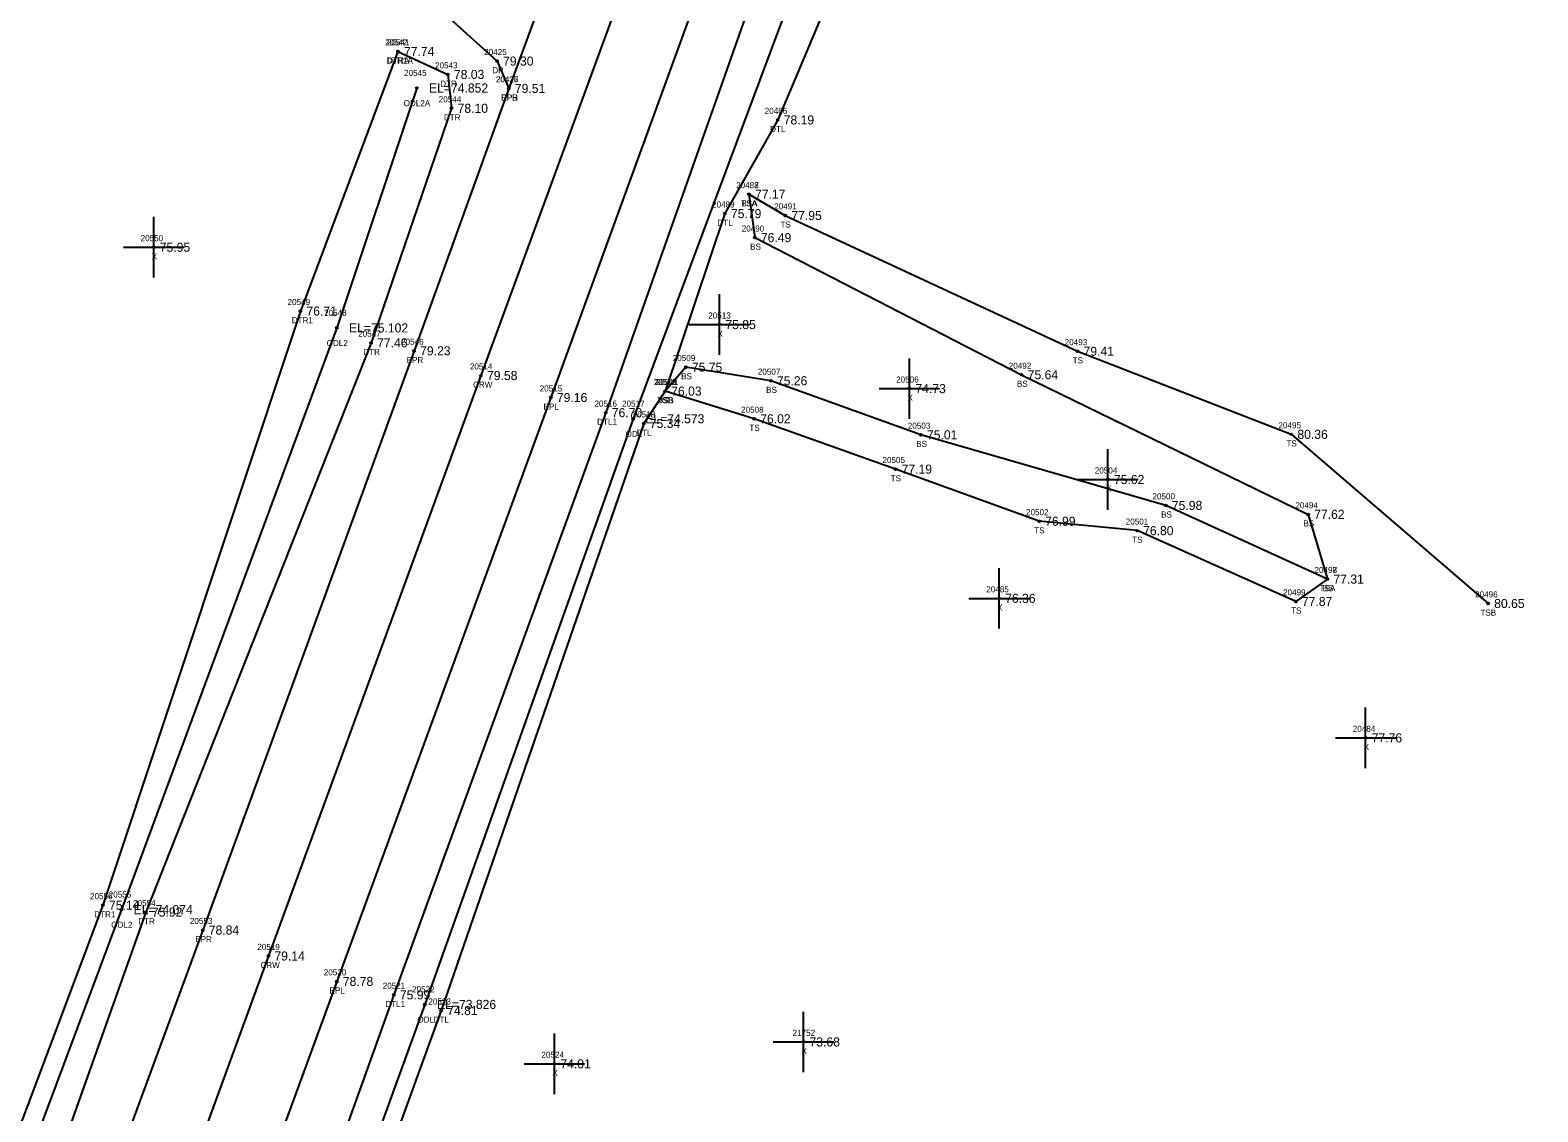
# Model space of a CAD drawing. Extents: x 2140110 to 2141565, y 506241 to 510327.
# Drawn here: x 2140964.5 to 2141213.4, y 509154.8 to 509333.5 of the extents above; entities that cross this region are included whole.
import ezdxf

# ---------------------------------------------------------------- set-up
doc = ezdxf.new("R2010")
doc.units = 0
for name, color, linetype in [('RD_DTM_BkLn1', 7, 'Continuous'), ('RD_DTM_BkLn2', 7, 'Continuous'), ('RD_DTM_BkLn_txCode', 7, 'Continuous'), ('RD_EX_Driveway', 7, 'Continuous'), ('RD_EX_Driveway_txCode', 7, 'Continuous'), ('RD_EX_H2O', 7, 'Continuous'), ('RD_EX_H2O_txCode', 7, 'Continuous'), ('RD_EX_Misc', 7, 'Continuous'), ('RD_EX_Misc_txCode', 7, 'Continuous'), ('RD_EX_Road', 7, 'Continuous'), ('RD_EX_Road_txCode', 7, 'Continuous'), ('RD_EX_TX_Driveway_ELEV', 7, 'Continuous'), ('RD_EX_TX_H2O_ELEV', 7, 'Continuous'), ('RD_EX_TX_Misc_ELEV', 7, 'Continuous'), ('RD_EX_TX_Road_ELEV', 7, 'Continuous'), ('RD_HC_Survey_ELEV', 7, 'Continuous'), ('RD_HC_Survey_txCode', 7, 'Continuous'), ('RD_SMD_Locator', 7, 'Continuous')]:
    doc.layers.add(name, color=color, linetype=linetype)

msp = doc.modelspace()

# ---------------------------------------------------------------- linework, layer by layer
at = {"layer": 'RD_DTM_BkLn1'}
msp.add_lwpolyline([(2141401.24, 510292.17), (2141386.62, 510241.55), (2141370.29, 510189.18), (2141352.34, 510135.64), (2141334.07, 510083.82), (2141314.82, 510031.25), (2141297.4, 509983.45), (2141260.01, 509880.66), (2141224.45, 509783.3), (2141187.1, 509681.41), (2141150.45, 509581.24), (2141112.96, 509478.26), (2141074.89, 509374.78), (2141038.89, 509276.46), (2141003.79, 509180.59), (2140969.89, 509087.8), (2140962.46, 509066.85), (2140921.91, 508956.12), (2140885.66, 508857.72), (2140850.55, 508762.05)], dxfattribs=at)
at = {"layer": 'RD_DTM_BkLn2'}
for points in [[(2141083.13, 509306.4), (2141084.1, 509299.24), (2141128.15, 509276.59), (2141175.44, 509253.53), (2141178.62, 509242.84), (2141151.95, 509255.01), (2141111.52, 509266.67), (2141086.75, 509275.6), (2141072.71, 509277.85), (2141069.29, 509273.89)], [(2141083.13, 509306.4), (2141089.13, 509302.9), (2141137.37, 509280.47), (2141172.67, 509266.75), (2141205.16, 509238.81)], [(2141178.62, 509242.84), (2141173.42, 509239.15), (2141147.2, 509250.84), (2141131.03, 509252.39), (2141107.33, 509261), (2141083.99, 509269.32), (2141069.29, 509273.89)]]:
    msp.add_lwpolyline(points, dxfattribs=at)
at = {"layer": 'RD_EX_Driveway'}
msp.add_lwpolyline([(2141052.52, 509348.48), (2141045.04, 509346.63), (2141037.37, 509348.41), (2141026.29, 509351.7), (2141022.22, 509343.44), (2141033.2, 509335.93), (2141041.54, 509328.4), (2141043.48, 509323.88)], dxfattribs=at)
at = {"layer": 'RD_EX_H2O'}
for points in [[(2141109.57, 509415.73), (2141114.37, 509420.62), (2141120.58, 509418.47), (2141123.73, 509414.72), (2141106.65, 509363.28), (2141087.87, 509318.68), (2141079.16, 509303.21), (2141069.29, 509273.89), (2141065.76, 509268.54), (2141032.31, 509171.57), (2140998.87, 509079.36), (2140999.1, 509067.34)], [(2141109.57, 509415.73), (2141094.19, 509368.74), (2141059.48, 509270.33), (2141024.5, 509174.17), (2140991.17, 509081.19), (2140987.7, 509072.11)], [(2141117.74, 509414.57), (2141100.21, 509366.33), (2141064.01, 509269.32), (2141029.63, 509172.59), (2140996.02, 509080.04), (2140996.76, 509067.73)], [(2141025.18, 509330), (2141009.08, 509287.11), (2140976.48, 509188.97), (2140943.34, 509100.91), (2140941.69, 509092.55)], [(2141025.18, 509330), (2141033.42, 509326.19), (2141034.03, 509320.6), (2141020.74, 509281.87), (2140983.57, 509187.83), (2140949.44, 509091.79), (2140950.12, 509084.29)], [(2141028.31, 509323.95), (2141015.1, 509284.32), (2140979.54, 509188.24), (2140943.06, 509090.7)]]:
    msp.add_lwpolyline(points, dxfattribs=at)
at = {"layer": 'RD_EX_Misc'}
for p, q in [((2140984.86, 509292.65), (2140984.86, 509302.65)), ((2140979.86, 509297.65), (2140989.86, 509297.65)), ((2141078.24, 509279.88), (2141078.24, 509289.88)), ((2141073.24, 509284.88), (2141083.24, 509284.88)), ((2141109.61, 509269.3), (2141109.61, 509279.3)), ((2141104.61, 509274.3), (2141114.61, 509274.3)), ((2141142.38, 509254.28), (2141142.38, 509264.28)), ((2141137.38, 509259.28), (2141147.38, 509259.28)), ((2141124.42, 509234.66), (2141124.42, 509244.66)), ((2141119.42, 509239.66), (2141129.42, 509239.66)), ((2141184.94, 509211.61), (2141184.94, 509221.61)), ((2141179.94, 509216.61), (2141189.94, 509216.61)), ((2141092.13, 509161.39), (2141092.13, 509171.39)), ((2141051, 509157.78), (2141051, 509167.78)), ((2141087.13, 509166.39), (2141097.13, 509166.39)), ((2141046, 509162.78), (2141056, 509162.78))]:
    msp.add_line(p, q, dxfattribs=at)
at = {"layer": 'RD_EX_Road'}
for points in [[(2141175.93, 509686.04), (2141140.09, 509588.3), (2141106.08, 509494.11), (2141096.82, 509469.24), (2141063.82, 509378.98), (2141052.52, 509348.48), (2141043.48, 509323.88), (2141027.84, 509280.54), (2140992.95, 509184.87), (2140958.53, 509091.45), (2140950.8, 509069.47), (2140944.28, 509052.06), (2140911.45, 508962.1), (2140874.65, 508861.6), (2140839.42, 508765.22), (2140802.38, 508664.56)], [(2141197.99, 509676.56), (2141193.66, 509664.6), (2141161.61, 509577.24), (2141123.75, 509473.61), (2141115.5, 509450.65), (2141102.09, 509414.61), (2141086.27, 509371.27), (2141050.42, 509272.83), (2141015.08, 509176.39), (2140981.03, 509083.35), (2140979.15, 509077.9), (2140973.7, 509063.54), (2140966.53, 509043.25), (2140933.44, 508952.99), (2140896.92, 508852.59), (2140862.18, 508757.77)]]:
    msp.add_lwpolyline(points, dxfattribs=at)
at = {"layer": 'RD_SMD_Locator'}
for centre in [(2141025.18, 509330), (2141025.18, 509330), (2141041.54, 509328.4), (2141033.42, 509326.19), (2141028.31, 509323.95), (2141043.48, 509323.88), (2141043.48, 509323.88), (2141034.03, 509320.6), (2141087.87, 509318.68), (2141083.13, 509306.4), (2141083.13, 509306.4), (2141079.16, 509303.21), (2141089.13, 509302.9), (2140984.86, 509297.65), (2141084.1, 509299.24), (2141009.08, 509287.11), (2141078.24, 509284.88), (2141015.1, 509284.32), (2141020.74, 509281.87), (2141027.84, 509280.54), (2141137.37, 509280.47), (2141072.71, 509277.85), (2141038.89, 509276.46), (2141086.75, 509275.6), (2141128.15, 509276.59), (2141050.42, 509272.83), (2141069.29, 509273.89), (2141069.29, 509273.89), (2141069.29, 509273.89), (2141109.61, 509274.3), (2141059.48, 509270.33), (2141064.01, 509269.32), (2141065.76, 509268.54), (2141083.99, 509269.32), (2141111.52, 509266.67), (2141172.67, 509266.75), (2141107.33, 509261), (2141142.38, 509259.28), (2141151.95, 509255.01), (2141131.03, 509252.39), (2141175.44, 509253.53), (2141147.2, 509250.84), (2141178.62, 509242.84), (2141178.62, 509242.84), (2141124.42, 509239.66), (2141173.42, 509239.15), (2141205.16, 509238.81), (2141184.94, 509216.61), (2140976.48, 509188.97), (2140979.54, 509188.24), (2140983.57, 509187.83), (2140992.95, 509184.87), (2141003.79, 509180.59), (2141015.08, 509176.39), (2141024.5, 509174.17), (2141029.63, 509172.59), (2141032.31, 509171.57), (2141092.13, 509166.39), (2141051, 509162.78)]:
    msp.add_circle(centre, 0.15, dxfattribs=at)

# ---------------------------------------------------------------- texts
at = {"layer": 'RD_DTM_BkLn_txCode'}
for s, p in [('20487', (2141081.01, 509307.4)), ('20488', (2141081.01, 509307.4)), ('TSA', (2141081.85, 509304.4)), ('BSA', (2141081.86, 509304.4)), ('20491', (2141087.29, 509303.9)), ('20490', (2141081.94, 509300.24)), ('TS', (2141088.33, 509300.9)), ('BS', (2141083.32, 509297.24)), ('20493', (2141135.25, 509281.47)), ('20509', (2141070.55, 509278.85)), ('20507', (2141084.6, 509276.6)), ('20492', (2141126.03, 509277.59)), ('TS', (2141136.57, 509278.47)), ('20510', (2141067.42, 509274.89)), ('20511', (2141067.74, 509274.89)), ('BS', (2141071.93, 509275.85)), ('BS', (2141127.37, 509274.59)), ('TSB', (2141068.02, 509271.89)), ('BSB', (2141068.04, 509271.89)), ('BS', (2141085.97, 509273.6)), ('20508', (2141081.83, 509270.32)), ('TS', (2141083.2, 509267.32)), ('20503', (2141109.36, 509267.67)), ('20495', (2141170.55, 509267.75)), ('BS', (2141110.74, 509264.67)), ('TS', (2141171.87, 509264.75)), ('20505', (2141105.17, 509262)), ('TS', (2141106.53, 509259)), ('20500', (2141149.75, 509256.01)), ('20494', (2141173.33, 509254.53)), ('20502', (2141128.87, 509253.39)), ('20501', (2141145.33, 509251.84)), ('BS', (2141151.17, 509253.01)), ('BS', (2141174.66, 509251.53)), ('TS', (2141130.23, 509250.39)), ('TS', (2141146.41, 509248.84)), ('20497', (2141176.5, 509243.84)), ('20498', (2141176.5, 509243.84)), ('20499', (2141171.3, 509240.15)), ('TSA', (2141177.34, 509240.84)), ('BS', (2141177.84, 509240.84)), ('20496', (2141203.01, 509239.81)), ('TS', (2141172.63, 509237.15)), ('TSB', (2141203.89, 509236.81))]:
    msp.add_text(s, height=1, dxfattribs=at).set_placement(p)
at = {"layer": 'RD_EX_Driveway_txCode'}
for s, p in [('20425', (2141039.42, 509329.4)), ('DP', (2141040.76, 509326.4)), ('20426', (2141041.33, 509324.88)), ('DPB', (2141042.22, 509321.88))]:
    msp.add_text(s, height=1, dxfattribs=at).set_placement(p)
at = {"layer": 'RD_EX_H2O_txCode'}
for s, p in [('20542', (2141023.06, 509331)), ('20541', (2141023.35, 509331)), ('DTR1A', (2141023.26, 509328)), ('DTRA', (2141023.42, 509328)), ('20543', (2141031.3, 509327.19)), ('20545', (2141026.19, 509325.95)), ('DTR', (2141032.16, 509324.19)), ('20544', (2141031.91, 509321.6)), ('ODL2A', (2141026.12, 509320.95)), ('DTR', (2141032.76, 509318.6)), ('20486', (2141085.73, 509319.68)), ('DTL', (2141086.63, 509316.68)), ('20489', (2141077.04, 509304.21)), ('DTL', (2141077.92, 509301.21)), ('20549', (2141006.96, 509288.11)), ('20548', (2141012.99, 509286.32)), ('DTR1', (2141007.65, 509285.11)), ('ODL2', (2141013.41, 509281.32)), ('20547', (2141018.62, 509282.87)), ('DTR', (2141019.47, 509279.87)), ('20512', (2141067.46, 509274.89)), ('20516', (2141057.62, 509271.33)), ('20517', (2141062.17, 509271.32)), ('DTL', (2141068.05, 509271.89)), ('20518', (2141063.93, 509269.54)), ('DTL1', (2141058.07, 509268.33)), ('ODL', (2141062.76, 509266.32)), ('DTL', (2141064.52, 509266.54)), ('20556', (2140974.34, 509189.97)), ('20555', (2140977.43, 509190.24)), ('DTR1', (2140975.05, 509186.97)), ('20554', (2140981.45, 509188.83)), ('ODL2', (2140977.85, 509185.24)), ('DTR', (2140982.3, 509185.83)), ('20521', (2141022.66, 509175.17)), ('20522', (2141027.51, 509174.59)), ('DTL1', (2141023.09, 509172.17)), ('20523', (2141030.2, 509172.57)), ('ODL', (2141028.39, 509169.59)), ('DTL', (2141031.07, 509169.57))]:
    msp.add_text(s, height=1, dxfattribs=at).set_placement(p)
at = {"layer": 'RD_EX_Misc_txCode'}
for s, p in [('20550', (2140982.7, 509298.65)), ('X', (2140984.54, 509295.65)), ('20513', (2141076.41, 509285.88)), ('X', (2141077.93, 509282.88)), ('20506', (2141107.43, 509275.3)), ('X', (2141109.3, 509272.3)), ('20504', (2141140.23, 509260.28)), ('X', (2141142.07, 509257.28)), ('20485', (2141122.31, 509240.66)), ('X', (2141124.11, 509237.66)), ('20484', (2141182.82, 509217.61)), ('X', (2141184.62, 509214.61)), ('21752', (2141090.33, 509167.39)), ('X', (2141091.81, 509164.39)), ('20524', (2141048.88, 509163.78)), ('X', (2141050.69, 509160.78))]:
    msp.add_text(s, height=1, dxfattribs=at).set_placement(p)
at = {"layer": 'RD_EX_Road_txCode'}
for s, p in [('20427', (2141041.36, 509324.88)), ('EPR', (2141042.25, 509321.88)), ('20546', (2141025.7, 509281.54)), ('EPR', (2141026.62, 509278.54)), ('20515', (2141048.58, 509273.83)), ('EPL', (2141049.21, 509270.83)), ('20553', (2140990.83, 509185.87)), ('EPR', (2140991.72, 509182.87)), ('20520', (2141012.93, 509177.39)), ('EPL', (2141013.88, 509174.39))]:
    msp.add_text(s, height=1, dxfattribs=at).set_placement(p)
at = {"layer": 'RD_EX_TX_Driveway_ELEV'}
for s, p in [('79.30', (2141042.54, 509327.65)), ('79.51', (2141044.48, 509323.13))]:
    msp.add_text(s, height=1.5, dxfattribs=at).set_placement(p)
at = {"layer": 'RD_EX_TX_H2O_ELEV'}
for s, p in [('77.74', (2141026.18, 509329.25)), ('77.74', (2141026.18, 509329.25)), ('EL=74.852', (2141030.31, 509323.2)), ('78.03', (2141034.42, 509325.44)), ('78.10', (2141035.03, 509319.85)), ('78.19', (2141088.87, 509317.93)), ('75.79', (2141080.16, 509302.46)), ('76.71', (2141010.08, 509286.36)), ('EL=75.102', (2141017.1, 509283.57)), ('77.46', (2141021.74, 509281.12)), ('76.03', (2141070.29, 509273.14)), ('76.70', (2141060.48, 509269.58)), ('EL=74.573', (2141066.01, 509268.57)), ('75.34', (2141066.76, 509267.79)), ('75.14', (2140977.48, 509188.22)), ('EL=74.074', (2140981.54, 509187.49)), ('75.92', (2140984.57, 509187.08)), ('75.99', (2141025.5, 509173.42)), ('EL=73.826', (2141031.63, 509171.84)), ('74.81', (2141033.31, 509170.82))]:
    msp.add_text(s, height=1.5, dxfattribs=at).set_placement(p)
at = {"layer": 'RD_EX_TX_Misc_ELEV'}
for s, p in [('77.17', (2141084.13, 509305.65)), ('77.17', (2141084.13, 509305.65)), ('77.95', (2141090.13, 509302.15)), ('76.49', (2141085.1, 509298.49)), ('75.95', (2140985.86, 509296.9)), ('75.85', (2141079.24, 509284.13)), ('79.41', (2141138.37, 509279.72)), ('75.75', (2141073.71, 509277.1)), ('75.64', (2141129.15, 509275.84)), ('75.26', (2141087.75, 509274.85)), ('74.73', (2141110.61, 509273.55)), ('76.03', (2141070.29, 509273.14)), ('76.03', (2141070.29, 509273.14)), ('76.02', (2141084.99, 509268.57)), ('75.01', (2141112.52, 509265.92)), ('80.36', (2141173.67, 509266)), ('77.19', (2141108.33, 509260.25)), ('75.62', (2141143.38, 509258.53)), ('75.98', (2141152.95, 509254.26)), ('76.99', (2141132.03, 509251.64)), ('77.62', (2141176.44, 509252.78)), ('76.80', (2141148.2, 509250.09)), ('77.31', (2141179.62, 509242.09)), ('77.31', (2141179.62, 509242.09)), ('76.36', (2141125.42, 509238.91)), ('77.87', (2141174.42, 509238.4)), ('80.65', (2141206.16, 509238.06)), ('77.76', (2141185.94, 509215.86)), ('73.68', (2141093.13, 509165.64)), ('74.01', (2141052, 509162.03))]:
    msp.add_text(s, height=1.5, dxfattribs=at).set_placement(p)
at = {"layer": 'RD_EX_TX_Road_ELEV'}
for s, p in [('79.51', (2141044.48, 509323.13)), ('79.23', (2141028.84, 509279.79)), ('79.16', (2141051.42, 509272.08)), ('78.84', (2140993.95, 509184.12)), ('78.78', (2141016.08, 509175.64))]:
    msp.add_text(s, height=1.5, dxfattribs=at).set_placement(p)
at = {"layer": 'RD_HC_Survey_ELEV'}
for s, p in [('79.58', (2141039.89, 509275.71)), ('79.14', (2141004.79, 509179.84))]:
    msp.add_text(s, height=1.5, dxfattribs=at).set_placement(p)
at = {"layer": 'RD_HC_Survey_txCode'}
for s, p in [('20514', (2141037.06, 509277.46)), ('CRW', (2141037.58, 509274.46)), ('20519', (2141001.96, 509181.59)), ('CRW', (2141002.48, 509178.59))]:
    msp.add_text(s, height=1, dxfattribs=at).set_placement(p)

doc.saveas('drawing.dxf')
